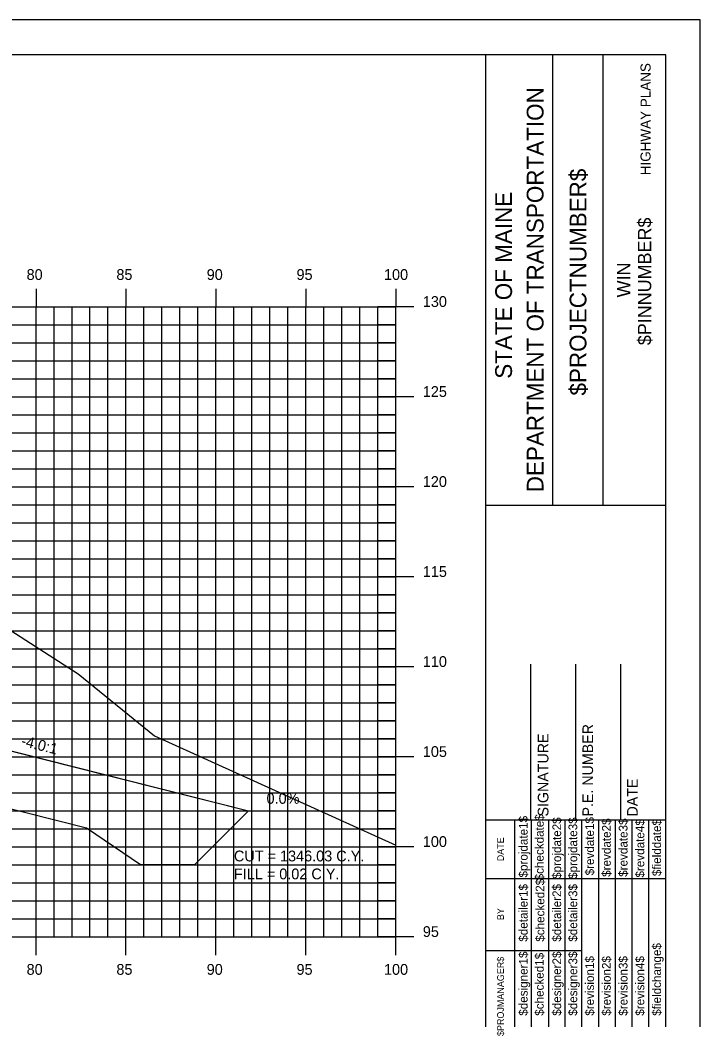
# Model space of a CAD drawing. Extents: x 850598 to 870284, y 366541 to 366651.
# Drawn here: x 853391.1 to 853428.9, y 366595.7 to 366651.2 of the extents above; entities that cross this region are included whole.
import ezdxf

# ---------------------------------------------------------------- set-up
doc = ezdxf.new("R2010")
doc.units = 0
for name, color, linetype in [('ANNOTATION', 7, 'Continuous'), ('BORDER', 7, 'Continuous'), ('D_Drainage_RipRap', 7, 'Continuous'), ('D_Roadway_Centerline', 7, 'Continuous'), ('D_Roadway_SlopeLines', 7, 'Continuous'), ('D_Text_Standard', 7, 'Continuous'), ('H_V ANNOTATION', 7, 'Continuous'), ('HIGHWAY_TITLE', 7, 'Continuous'), ('MAJOR', 7, 'Continuous'), ('MINOR', 7, 'Continuous'), ('PLOT BOUNDARY', 7, 'Continuous'), ('S_Roadway_Centerline', 7, 'Continuous')]:
    doc.layers.add(name, color=color, linetype=linetype)

msp = doc.modelspace()

# ---------------------------------------------------------------- linework, layer by layer
at = {"layer": 'BORDER'}
for p, q in [((853426.976, 366649.225), (853266.976, 366649.225)), ((853416.976, 366544.225), (853416.976, 366649.225)), ((853420.704, 366624.222), (853420.704, 366649.222)), ((853423.499, 366624.222), (853423.499, 366649.222)), ((853426.976, 366544.225), (853426.976, 366649.225)), ((853416.977, 366624.219), (853426.976, 366624.219)), ((853419.476, 366606.728), (853419.476, 366615.376)), ((853421.976, 366606.728), (853421.976, 366615.376)), ((853424.476, 366606.728), (853424.476, 366615.376)), ((853416.976, 366606.728), (853426.976, 366606.728))]:
    msp.add_line(p, q, dxfattribs=at)
for points in [[(853418.591, 366603.478), (853418.591, 366606.728)], [(853419.523, 366589.231), (853419.523, 366606.728)], [(853420.455, 366606.728), (853420.455, 366589.231)], [(853421.386, 366589.231), (853421.386, 366606.728)], [(853422.318, 366589.231), (853422.318, 366606.728)], [(853423.25, 366589.231), (853423.25, 366606.728)], [(853424.182, 366589.231), (853424.182, 366606.728)], [(853425.113, 366589.231), (853425.113, 366606.728)], [(853426.045, 366589.231), (853426.045, 366606.728)], [(853418.591, 366589.231), (853418.591, 366606.022)], [(853416.976, 366603.478), (853426.976, 366603.478)], [(853416.976, 366599.478), (853418.591, 366599.478)], [(853418.591, 366599.478), (853422.317, 366599.478)]]:
    msp.add_lwpolyline(points, dxfattribs=at)
at = {"layer": 'D_Drainage_RipRap'}
msp.add_lwpolyline([(853380.04, 366613.225), (853393.921, 366609.718), (853403.783, 366607.225), (853400.783, 366604.225), (853397.783, 366604.225), (853394.783, 366606.268), (853380.902, 366609.775), (853380.04, 366611.725), (853334.975, 366623.114), (853334.975, 366624.614)], close=True, dxfattribs=at)
at = {"layer": 'D_Roadway_Centerline'}
msp.add_lwpolyline([(853290.778, 366624.668), (853296.975, 366626.734), (853300.975, 366626.974), (853311.975, 366627.304), (853322.975, 366626.974), (853326.975, 366626.734), (853328.975, 366626.614), (853334.975, 366624.614), (853380.04, 366613.225), (853393.921, 366609.718), (853403.783, 366607.225), (853407.783, 366607.225)], dxfattribs=at)
at = {"layer": 'D_Roadway_SlopeLines'}
msp.add_lwpolyline([(853334.975, 366624.614), (853403.783, 366607.225), (853403.783, 366607.225)], dxfattribs=at)
at = {"layer": 'MAJOR'}
for p, q in [((853391.975, 366636.227), (853391.975, 366635.225)), ((853391.975, 366636.227), (853391.975, 366635.225)), ((853396.975, 366636.227), (853396.975, 366635.225)), ((853396.975, 366636.227), (853396.975, 366635.225)), ((853401.975, 366636.227), (853401.975, 366635.225)), ((853401.975, 366636.227), (853401.975, 366635.225)), ((853406.975, 366636.227), (853406.975, 366635.225)), ((853406.975, 366636.227), (853406.975, 366635.225)), ((853411.975, 366636.227), (853411.975, 366635.225)), ((853411.975, 366636.227), (853411.975, 366635.225)), ((853271.975, 366635.225), (853411.975, 366635.225)), ((853271.975, 366635.225), (853411.975, 366635.225)), ((853271.975, 366635.225), (853411.975, 366635.225)), ((853271.975, 366635.225), (853411.975, 366635.225)), ((853391.975, 366600.225), (853391.975, 366635.225)), ((853391.975, 366600.225), (853391.975, 366635.225)), ((853396.975, 366600.225), (853396.975, 366635.225)), ((853396.975, 366600.225), (853396.975, 366635.225)), ((853401.975, 366600.225), (853401.975, 366635.225)), ((853401.975, 366600.225), (853401.975, 366635.225)), ((853406.975, 366600.225), (853406.975, 366635.225)), ((853406.975, 366600.225), (853406.975, 366635.225)), ((853412.977, 366635.225), (853410.973, 366635.225)), ((853412.977, 366635.225), (853410.973, 366635.225)), ((853411.975, 366600.225), (853411.975, 366635.225)), ((853411.975, 366600.225), (853411.975, 366635.225)), ((853411.975, 366600.225), (853411.975, 366635.225)), ((853411.975, 366600.225), (853411.975, 366635.225)), ((853271.975, 366630.225), (853411.975, 366630.225)), ((853271.975, 366630.225), (853411.975, 366630.225)), ((853412.977, 366630.225), (853410.973, 366630.225)), ((853412.977, 366630.225), (853410.973, 366630.225)), ((853271.975, 366625.225), (853411.975, 366625.225)), ((853271.975, 366625.225), (853411.975, 366625.225)), ((853412.977, 366625.225), (853410.973, 366625.225)), ((853412.977, 366625.225), (853410.973, 366625.225)), ((853271.975, 366620.225), (853411.975, 366620.225)), ((853271.975, 366620.225), (853411.975, 366620.225)), ((853412.977, 366620.225), (853410.973, 366620.225)), ((853412.977, 366620.225), (853410.973, 366620.225)), ((853271.975, 366615.225), (853411.975, 366615.225)), ((853271.975, 366615.225), (853411.975, 366615.225)), ((853412.977, 366615.225), (853410.973, 366615.225)), ((853412.977, 366615.225), (853410.973, 366615.225)), ((853271.975, 366610.225), (853411.975, 366610.225)), ((853271.975, 366610.225), (853411.975, 366610.225)), ((853412.977, 366610.225), (853410.973, 366610.225)), ((853412.977, 366610.225), (853410.973, 366610.225)), ((853271.975, 366605.225), (853411.975, 366605.225)), ((853271.975, 366605.225), (853411.975, 366605.225)), ((853412.977, 366605.225), (853410.973, 366605.225)), ((853412.977, 366605.225), (853410.973, 366605.225)), ((853271.975, 366600.225), (853411.975, 366600.225)), ((853271.975, 366600.225), (853411.975, 366600.225)), ((853271.975, 366600.225), (853411.975, 366600.225)), ((853271.975, 366600.225), (853411.975, 366600.225)), ((853391.975, 366599.223), (853391.975, 366600.225)), ((853391.975, 366599.223), (853391.975, 366600.225)), ((853396.975, 366599.223), (853396.975, 366600.225)), ((853396.975, 366599.223), (853396.975, 366600.225)), ((853401.975, 366599.223), (853401.975, 366600.225)), ((853401.975, 366599.223), (853401.975, 366600.225)), ((853406.975, 366599.223), (853406.975, 366600.225)), ((853406.975, 366599.223), (853406.975, 366600.225)), ((853412.977, 366600.225), (853410.973, 366600.225)), ((853412.977, 366600.225), (853410.973, 366600.225)), ((853411.975, 366599.223), (853411.975, 366600.225)), ((853411.975, 366599.223), (853411.975, 366600.225))]:
    msp.add_line(p, q, dxfattribs=at)
at = {"layer": 'MINOR'}
for p, q in [((853392.975, 366600.225), (853392.975, 366635.225)), ((853392.975, 366600.225), (853392.975, 366635.225)), ((853393.975, 366600.225), (853393.975, 366635.225)), ((853393.975, 366600.225), (853393.975, 366635.225)), ((853394.975, 366600.225), (853394.975, 366635.225)), ((853394.975, 366600.225), (853394.975, 366635.225)), ((853395.975, 366600.225), (853395.975, 366635.225)), ((853395.975, 366600.225), (853395.975, 366635.225)), ((853397.975, 366600.225), (853397.975, 366635.225)), ((853397.975, 366600.225), (853397.975, 366635.225)), ((853398.975, 366600.225), (853398.975, 366635.225)), ((853398.975, 366600.225), (853398.975, 366635.225)), ((853399.975, 366600.225), (853399.975, 366635.225)), ((853399.975, 366600.225), (853399.975, 366635.225)), ((853400.975, 366600.225), (853400.975, 366635.225)), ((853400.975, 366600.225), (853400.975, 366635.225)), ((853402.975, 366600.225), (853402.975, 366635.225)), ((853402.975, 366600.225), (853402.975, 366635.225)), ((853403.975, 366600.225), (853403.975, 366635.225)), ((853403.975, 366600.225), (853403.975, 366635.225)), ((853404.975, 366600.225), (853404.975, 366635.225)), ((853404.975, 366600.225), (853404.975, 366635.225)), ((853405.975, 366600.225), (853405.975, 366635.225)), ((853405.975, 366600.225), (853405.975, 366635.225)), ((853407.975, 366600.225), (853407.975, 366635.225)), ((853407.975, 366600.225), (853407.975, 366635.225)), ((853408.975, 366600.225), (853408.975, 366635.225)), ((853408.975, 366600.225), (853408.975, 366635.225)), ((853409.975, 366600.225), (853409.975, 366635.225)), ((853409.975, 366600.225), (853409.975, 366635.225)), ((853410.975, 366600.225), (853410.975, 366635.225)), ((853410.975, 366600.225), (853410.975, 366635.225)), ((853271.975, 366634.225), (853411.975, 366634.225)), ((853271.975, 366634.225), (853411.975, 366634.225)), ((853411.975, 366634.225), (853410.973, 366634.225)), ((853411.975, 366634.225), (853410.973, 366634.225)), ((853271.975, 366633.225), (853411.975, 366633.225)), ((853271.975, 366633.225), (853411.975, 366633.225)), ((853411.975, 366633.225), (853410.973, 366633.225)), ((853411.975, 366633.225), (853410.973, 366633.225)), ((853271.975, 366632.225), (853411.975, 366632.225)), ((853271.975, 366632.225), (853411.975, 366632.225)), ((853411.975, 366632.225), (853410.973, 366632.225)), ((853411.975, 366632.225), (853410.973, 366632.225)), ((853271.975, 366631.225), (853411.975, 366631.225)), ((853271.975, 366631.225), (853411.975, 366631.225)), ((853411.975, 366631.225), (853410.973, 366631.225)), ((853411.975, 366631.225), (853410.973, 366631.225)), ((853271.975, 366629.225), (853411.975, 366629.225)), ((853271.975, 366629.225), (853411.975, 366629.225)), ((853411.975, 366629.225), (853410.973, 366629.225)), ((853411.975, 366629.225), (853410.973, 366629.225)), ((853271.975, 366628.225), (853411.975, 366628.225)), ((853271.975, 366628.225), (853411.975, 366628.225)), ((853411.975, 366628.225), (853410.973, 366628.225)), ((853411.975, 366628.225), (853410.973, 366628.225)), ((853271.975, 366627.225), (853411.975, 366627.225)), ((853271.975, 366627.225), (853411.975, 366627.225)), ((853411.975, 366627.225), (853410.973, 366627.225)), ((853411.975, 366627.225), (853410.973, 366627.225)), ((853271.975, 366626.225), (853411.975, 366626.225)), ((853271.975, 366626.225), (853411.975, 366626.225)), ((853411.975, 366626.225), (853410.973, 366626.225)), ((853411.975, 366626.225), (853410.973, 366626.225)), ((853271.975, 366624.225), (853411.975, 366624.225)), ((853271.975, 366624.225), (853411.975, 366624.225)), ((853411.975, 366624.225), (853410.973, 366624.225)), ((853411.975, 366624.225), (853410.973, 366624.225)), ((853271.975, 366623.225), (853411.975, 366623.225)), ((853271.975, 366623.225), (853411.975, 366623.225)), ((853411.975, 366623.225), (853410.973, 366623.225)), ((853411.975, 366623.225), (853410.973, 366623.225)), ((853271.975, 366622.225), (853411.975, 366622.225)), ((853271.975, 366622.225), (853411.975, 366622.225)), ((853411.975, 366622.225), (853410.973, 366622.225)), ((853411.975, 366622.225), (853410.973, 366622.225)), ((853271.975, 366621.225), (853411.975, 366621.225)), ((853271.975, 366621.225), (853411.975, 366621.225)), ((853411.975, 366621.225), (853410.973, 366621.225)), ((853411.975, 366621.225), (853410.973, 366621.225)), ((853271.975, 366619.225), (853411.975, 366619.225)), ((853271.975, 366619.225), (853411.975, 366619.225)), ((853411.975, 366619.225), (853410.973, 366619.225)), ((853411.975, 366619.225), (853410.973, 366619.225)), ((853271.975, 366618.225), (853411.975, 366618.225)), ((853271.975, 366618.225), (853411.975, 366618.225)), ((853411.975, 366618.225), (853410.973, 366618.225)), ((853411.975, 366618.225), (853410.973, 366618.225)), ((853271.975, 366617.225), (853411.975, 366617.225)), ((853271.975, 366617.225), (853411.975, 366617.225)), ((853411.975, 366617.225), (853410.973, 366617.225)), ((853411.975, 366617.225), (853410.973, 366617.225)), ((853271.975, 366616.225), (853411.975, 366616.225)), ((853271.975, 366616.225), (853411.975, 366616.225)), ((853411.975, 366616.225), (853410.973, 366616.225)), ((853411.975, 366616.225), (853410.973, 366616.225)), ((853271.975, 366614.225), (853411.975, 366614.225)), ((853271.975, 366614.225), (853411.975, 366614.225)), ((853411.975, 366614.225), (853410.973, 366614.225)), ((853411.975, 366614.225), (853410.973, 366614.225)), ((853271.975, 366613.225), (853411.975, 366613.225)), ((853271.975, 366613.225), (853411.975, 366613.225)), ((853411.975, 366613.225), (853410.973, 366613.225)), ((853411.975, 366613.225), (853410.973, 366613.225)), ((853271.975, 366612.225), (853411.975, 366612.225)), ((853271.975, 366612.225), (853411.975, 366612.225)), ((853411.975, 366612.225), (853410.973, 366612.225)), ((853411.975, 366612.225), (853410.973, 366612.225)), ((853271.975, 366611.225), (853411.975, 366611.225)), ((853271.975, 366611.225), (853411.975, 366611.225)), ((853411.975, 366611.225), (853410.973, 366611.225)), ((853411.975, 366611.225), (853410.973, 366611.225)), ((853271.975, 366609.225), (853411.975, 366609.225)), ((853271.975, 366609.225), (853411.975, 366609.225)), ((853411.975, 366609.225), (853410.973, 366609.225)), ((853411.975, 366609.225), (853410.973, 366609.225)), ((853271.975, 366608.225), (853411.975, 366608.225)), ((853271.975, 366608.225), (853411.975, 366608.225)), ((853411.975, 366608.225), (853410.973, 366608.225)), ((853411.975, 366608.225), (853410.973, 366608.225)), ((853271.975, 366607.225), (853411.975, 366607.225)), ((853271.975, 366607.225), (853411.975, 366607.225)), ((853411.975, 366607.225), (853410.973, 366607.225)), ((853411.975, 366607.225), (853410.973, 366607.225)), ((853271.975, 366606.225), (853411.975, 366606.225)), ((853271.975, 366606.225), (853411.975, 366606.225)), ((853411.975, 366606.225), (853410.973, 366606.225)), ((853411.975, 366606.225), (853410.973, 366606.225)), ((853271.975, 366604.225), (853411.975, 366604.225)), ((853271.975, 366604.225), (853411.975, 366604.225)), ((853411.975, 366604.225), (853410.973, 366604.225)), ((853411.975, 366604.225), (853410.973, 366604.225)), ((853271.975, 366603.225), (853411.975, 366603.225)), ((853271.975, 366603.225), (853411.975, 366603.225)), ((853411.975, 366603.225), (853410.973, 366603.225)), ((853411.975, 366603.225), (853410.973, 366603.225)), ((853271.975, 366602.225), (853411.975, 366602.225)), ((853271.975, 366602.225), (853411.975, 366602.225)), ((853411.975, 366602.225), (853410.973, 366602.225)), ((853411.975, 366602.225), (853410.973, 366602.225)), ((853271.975, 366601.225), (853411.975, 366601.225)), ((853271.975, 366601.225), (853411.975, 366601.225)), ((853411.975, 366601.225), (853410.973, 366601.225)), ((853411.975, 366601.225), (853410.973, 366601.225))]:
    msp.add_line(p, q, dxfattribs=at)
at = {"layer": 'PLOT BOUNDARY'}
msp.add_lwpolyline([(853258.882, 366541.166), (853428.882, 366541.166), (853428.882, 366651.166), (853258.882, 366651.166)], close=True, dxfattribs=at)
at = {"layer": 'S_Roadway_Centerline'}
msp.add_lwpolyline([(853350.778, 366626.442), (853358.928, 366626.82), (853366.359, 366626.626), (853374.996, 366626.455), (853381.829, 366624.325), (853381.892, 366624.307), (853382.124, 366624.135), (853388.166, 366618.783), (853394.309, 366614.853), (853398.564, 366611.392), (853411.975, 366605.33)], dxfattribs=at)

# ---------------------------------------------------------------- texts
at = {"layer": 'ANNOTATION'}
msp.add_text('-4.0:1', height=0.6, rotation=345.8176, dxfattribs=at).set_placement((853391.107, 366610.86))
msp.add_text('0.0%', height=0.6, dxfattribs=at).set_placement((853404.788, 366607.625))
at = {"layer": 'BORDER'}
for s, height, p in [('DEPARTMENT OF TRANSPORTATION', 0.93176, (853420.182, 366624.931)), ('$PROJECTNUMBER$', 0.93176, (853422.568, 366630.304)), ('STATE OF MAINE', 0.93176, (853418.431, 366631.237)), ('$PINNUMBER$', 0.74527, (853426.171, 366633.1)), ('WIN', 0.7453, (853425.012, 366635.755)), ('P.E. NUMBER', 0.59055, (853422.936, 366606.92)), ('SIGNATURE', 0.5906, (853420.456, 366606.92)), ('DATE', 0.5906, (853425.417, 366606.92)), ('$projdate1$', 0.48455, (853419.299, 366603.529)), ('$checkdate$', 0.48455, (853420.193, 366603.371)), ('$projdate2$', 0.48455, (853421.162, 366603.45)), ('$projdate3$', 0.48455, (853422.056, 366603.45)), ('$revdate1$', 0.4845, (853422.988, 366603.647)), ('$revdate2$', 0.4845, (853423.92, 366603.568)), ('$revdate3$', 0.4845, (853424.851, 366603.568)), ('$revdate4$', 0.4845, (853425.783, 366603.529)), ('$fielddate$', 0.48455, (853426.715, 366603.607)), ('DATE', 0.3714, (853417.98, 366604.434)), ('$checked2$', 0.4845, (853420.23, 366599.963)), ('$detailer1$', 0.48455, (853419.299, 366599.963)), ('$detailer2$', 0.48455, (853421.162, 366599.963)), ('$detailer3$', 0.48455, (853422.056, 366599.963)), ('BY', 0.3714, (853417.98, 366601.163)), ('$fieldchange$', 0.48455, (853426.715, 366595.851)), ('$designer1$', 0.48455, (853419.299, 366595.851)), ('$checked1$', 0.4845, (853420.193, 366595.851)), ('$designer2$', 0.48455, (853421.162, 366595.851)), ('$designer3$', 0.48455, (853422.056, 366595.851)), ('$PROJMANAGER$', 0.37275, (853417.98, 366594.723)), ('$revision1$', 0.48455, (853422.988, 366595.851)), ('$revision2$', 0.48455, (853423.92, 366595.851)), ('$revision3$', 0.48455, (853424.851, 366595.851)), ('$revision4$', 0.48455, (853425.783, 366595.851))]:
    msp.add_text(s, height=height, rotation=90, dxfattribs=at).set_placement(p)
at = {"layer": 'D_Text_Standard'}
for s, p in [('CUT = 1346.03 C.Y.', (853402.975, 366604.425)), ('FILL = 0.02 C.Y.', (853402.975, 366603.429))]:
    msp.add_text(s, height=0.6, dxfattribs=at).set_placement(p)
at = {"layer": 'H_V ANNOTATION'}
for s, p in [('80', (853391.451, 366636.725)), ('85', (853396.443, 366636.725)), ('90', (853401.462, 366636.725)), ('95', (853406.454, 366636.725)), ('100', (853411.317, 366636.725)), ('130', (853413.475, 366635.225)), ('125', (853413.475, 366630.225)), ('120', (853413.475, 366625.225)), ('115', (853413.475, 366620.225)), ('110', (853413.475, 366615.225)), ('105', (853413.475, 366610.225)), ('100', (853413.475, 366605.225)), ('95', (853413.475, 366600.225)), ('80', (853391.451, 366598.125)), ('85', (853396.443, 366598.125)), ('90', (853401.462, 366598.125)), ('95', (853406.454, 366598.125)), ('100', (853411.317, 366598.125))]:
    msp.add_text(s, height=0.6, dxfattribs=at).set_placement(p)
at = {"layer": 'HIGHWAY_TITLE'}
msp.add_text('HIGHWAY PLANS', height=0.55901, rotation=90, dxfattribs=at).set_placement((853426.134, 366642.541))

doc.saveas('drawing.dxf')
